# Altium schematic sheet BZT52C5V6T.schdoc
size 127 x 101 mm
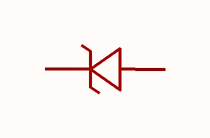
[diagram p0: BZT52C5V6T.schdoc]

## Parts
D?  bzt52c5v6t  [SOD-523_L1.2-W0.8-LS1.6-RD]  (value not drawn)

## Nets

Not connected (* = marked no-connect by the designer): D? 1(K) 2(A)

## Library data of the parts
D? = bzt52c5v6t: 二极管配置:1个独立式;稳压值(标称值):5.6V;稳压值(范围值):5.2V~6V;耗散功率(Pd):200mW;; Manufacturer: MDD(辰达半导体); AddInBom: yes; ModelId: 8f56a03db567494d8f4c9d12aa52a741; ModelName: SOD-523_L1.2-W0.8-H0.7-LS1.6; ModelTransform: 62.992,31.496,0,180,0,0,0,0,0; Diode Configuration: 1个独立式; Zener Voltage(Nom): 5.6V; Reverse Leakage Current (Ir): 1uA@2V; Pd - Power Dissipation: 200mW; Impedance(Zzt): 40Ω; Impedance(Zzk): 400Ω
